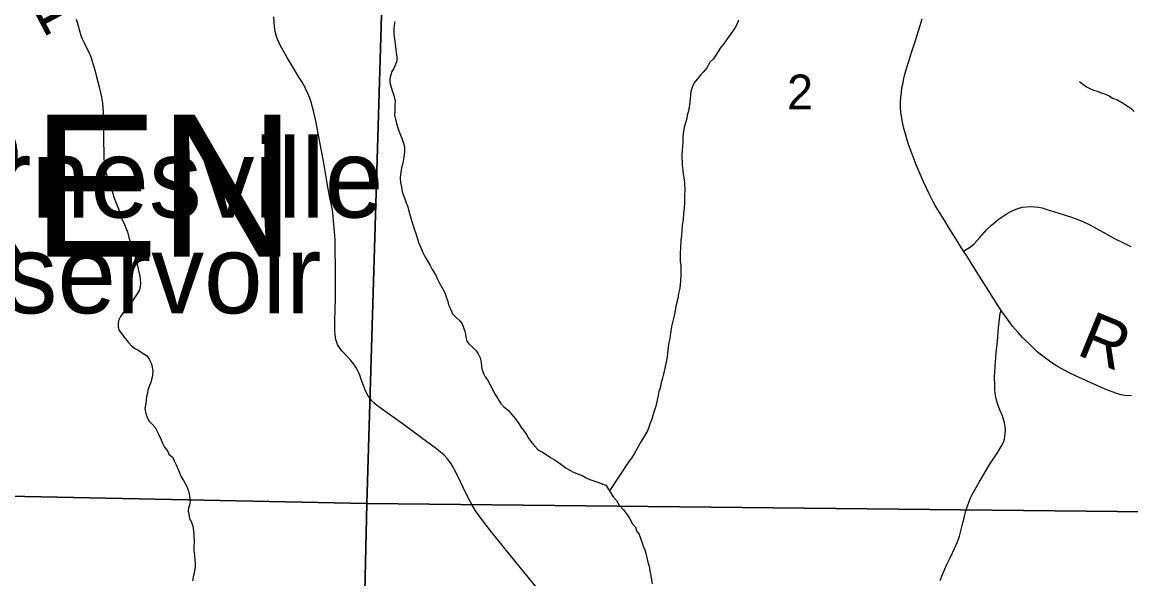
# Model space of a CAD drawing. Extents: x -7.9 to 76.1, y 0 to 22.
# Drawn here: x 4.02 to 5.35, y 19.16 to 19.828 of the extents above; entities that cross this region are included whole.
import ezdxf

# ---------------------------------------------------------------- set-up
doc = ezdxf.new("R2010")
doc.units = 0
for name, color, linetype in [('GM_X_County_Road', 7, 'Continuous'), ('GM_X_County_Road_Text', 7, 'Continuous'), ('GM_X_Minor_Lake_Text', 7, 'Continuous'), ('GM_X_Minor_River', 7, 'Continuous'), ('GM_X_Section', 7, 'Continuous'), ('GM_X_Section_Text', 7, 'Continuous'), ('GM_X_Township_Road', 7, 'Continuous'), ('GM_X_Township_Road_Text', 7, 'Continuous'), ('GM_X_Township_Text', 7, 'Continuous')]:
    doc.layers.add(name, color=color, linetype=linetype)

msp = doc.modelspace()

# ---------------------------------------------------------------- linework, layer by layer
at = {"layer": 'GM_X_County_Road'}
for points in [[(5.1493, 19.5533), (5.141, 19.5668), (5.1323, 19.5807), (5.127, 19.5893), (5.1186, 19.6025), (5.1154, 19.6078), (5.1126, 19.6129), (5.1088, 19.6203), (5.1013, 19.6361), (5.0972, 19.6456), (5.0926, 19.6565), (5.0877, 19.6696), (5.0835, 19.681), (5.0809, 19.6893), (5.0792, 19.6952), (5.0775, 19.7019), (5.0757, 19.7099), (5.0748, 19.715), (5.0743, 19.7195), (5.0739, 19.7255), (5.0738, 19.7324), (5.0741, 19.738), (5.0748, 19.7439), (5.0755, 19.7489), (5.0764, 19.7536), (5.0778, 19.7604), (5.0791, 19.7656), (5.0833, 19.7797), (5.0873, 19.7926), (5.0908, 19.8035), (5.0952, 19.8173), (5.0997, 19.8317)], [(5.1946, 19.4819), (5.1882, 19.4919), (5.1825, 19.5008), (5.1768, 19.5099), (5.1695, 19.5215), (5.1629, 19.5318), (5.1544, 19.5454), (5.1493, 19.5533)], [(5.3509, 19.3797), (5.3429, 19.3801), (5.3386, 19.3809), (5.3343, 19.382), (5.3288, 19.3839), (5.3221, 19.3865), (5.3013, 19.3957), (5.2779, 19.4065), (5.2711, 19.4099), (5.2628, 19.4144), (5.2576, 19.4176), (5.2525, 19.4212), (5.2465, 19.4257), (5.2379, 19.4325), (5.2282, 19.4418), (5.2203, 19.4496), (5.2148, 19.4557), (5.2082, 19.4633), (5.202, 19.4714), (5.1946, 19.4819)]]:
    msp.add_lwpolyline(points, dxfattribs=at)
at = {"layer": 'GM_X_Minor_River'}
for points in [[(4.0849, 19.8316), (4.0865, 19.8267), (4.0885, 19.8192), (4.0905, 19.812), (4.0921, 19.8079), (4.0949, 19.8022), (4.0972, 19.797), (4.1004, 19.7909), (4.1023, 19.7861), (4.1039, 19.7812), (4.1063, 19.7729), (4.1079, 19.7676), (4.1092, 19.7623), (4.1124, 19.7502), (4.1153, 19.7378), (4.1162, 19.7306), (4.1166, 19.7253), (4.1171, 19.7204), (4.1181, 19.6639), (4.1186, 19.6575), (4.1194, 19.6514), (4.1206, 19.6461), (4.1222, 19.6416), (4.1242, 19.6356), (4.1262, 19.6299), (4.1278, 19.625), (4.1298, 19.6178), (4.1326, 19.6107), (4.1354, 19.6039), (4.137, 19.599), (4.1401, 19.5907), (4.1425, 19.5862), (4.1441, 19.5817), (4.1464, 19.5764), (4.1481, 19.5696), (4.1501, 19.5636), (4.1521, 19.5572), (4.154, 19.5523), (4.1553, 19.5474), (4.1569, 19.5429), (4.1581, 19.5384), (4.1589, 19.5334), (4.1601, 19.5282), (4.161, 19.5232), (4.1614, 19.5195), (4.1619, 19.5145), (4.1616, 19.5107), (4.1609, 19.5069), (4.1572, 19.5008), (4.1532, 19.4947), (4.1491, 19.4893)], [(4.4671, 19.8288), (4.4661, 19.8239), (4.4658, 19.8197), (4.4659, 19.8144), (4.4663, 19.8103), (4.4672, 19.805), (4.4676, 19.8012), (4.4681, 19.7955), (4.4685, 19.7906), (4.4694, 19.7861), (4.4695, 19.7815), (4.468, 19.7769), (4.4658, 19.7723), (4.4636, 19.7685), (4.4622, 19.7647), (4.4611, 19.7601), (4.4612, 19.7556), (4.464, 19.7458), (4.4656, 19.7416), (4.4668, 19.7371), (4.4673, 19.7333), (4.467, 19.728), (4.4671, 19.7216), (4.4668, 19.7163), (4.468, 19.7114), (4.4689, 19.7064), (4.4712, 19.7)], [(4.8795, 19.8304), (4.8777, 19.8258), (4.8752, 19.8216), (4.8722, 19.8166), (4.867, 19.8093), (4.8615, 19.8013), (4.8574, 19.7966), (4.8552, 19.7928), (4.8493, 19.784), (4.8449, 19.7797), (4.8419, 19.7736), (4.8371, 19.7679), (4.8334, 19.764), (4.8297, 19.7594), (4.8264, 19.7552), (4.8242, 19.7506), (4.8224, 19.7445), (4.8214, 19.7357), (4.8208, 19.7285), (4.8194, 19.7209), (4.8179, 19.7164), (4.8173, 19.7122), (4.8144, 19.7019), (4.8134, 19.6966), (4.8127, 19.6905), (4.8125, 19.6833), (4.8119, 19.6738), (4.8116, 19.6681), (4.8118, 19.6567), (4.8127, 19.6503), (4.8131, 19.6458), (4.8139, 19.6416), (4.8148, 19.6348), (4.815, 19.6257), (4.8147, 19.6204), (4.8147, 19.6166), (4.8145, 19.6113), (4.8142, 19.6048), (4.8136, 19.5984), (4.8129, 19.5908), (4.8119, 19.5843), (4.8116, 19.5786), (4.811, 19.5718), (4.8103, 19.5665), (4.8097, 19.5562), (4.8094, 19.5517), (4.8096, 19.5403), (4.8101, 19.5362), (4.8103, 19.5248), (4.81, 19.5172), (4.809, 19.5088), (4.8076, 19.5024), (4.8066, 19.4963), (4.8041, 19.4871), (4.8035, 19.4822), (4.8021, 19.4757), (4.8003, 19.4674), (4.7992, 19.4628), (4.7979, 19.4548), (4.7969, 19.4484), (4.7958, 19.4434), (4.7951, 19.4381), (4.7941, 19.4309), (4.7938, 19.4263), (4.7928, 19.4202), (4.791, 19.4126), (4.7893, 19.4054), (4.7882, 19.4008)], [(5.2886, 19.7567), (5.2924, 19.7534), (5.297, 19.7504), (5.3016, 19.7478), (5.3054, 19.7464), (5.31, 19.7449), (5.3146, 19.7431), (5.3184, 19.742), (5.3241, 19.7394), (5.3283, 19.7368), (5.3333, 19.735), (5.3409, 19.7305), (5.3451, 19.7279), (5.3501, 19.7246), (5.3543, 19.7205)], [(4.4712, 19.7), (4.4732, 19.6944), (4.4756, 19.6887), (4.4776, 19.6827), (4.4788, 19.6782), (4.4785, 19.6725), (4.4779, 19.6657), (4.4765, 19.6588), (4.4751, 19.6531), (4.4737, 19.6455), (4.4734, 19.6402), (4.4739, 19.6353), (4.4751, 19.63), (4.4759, 19.6247), (4.4771, 19.6209), (4.4791, 19.616), (4.4807, 19.6111), (4.4827, 19.6062), (4.4839, 19.6009), (4.4855, 19.5953), (4.4871, 19.59), (4.4887, 19.5851), (4.4903, 19.5798), (4.4923, 19.5742), (4.4943, 19.5681), (4.4955, 19.5636), (4.4979, 19.5584), (4.5007, 19.5516), (4.5034, 19.5459), (4.5065, 19.5407), (4.5096, 19.5358), (4.512, 19.5313), (4.5163, 19.5242), (4.5179, 19.5204), (4.5206, 19.5148), (4.5241, 19.5084), (4.5269, 19.5031), (4.5288, 19.4982), (4.5305, 19.4926), (4.5313, 19.4888), (4.5344, 19.4832), (4.5364, 19.4779), (4.5402, 19.4738), (4.5441, 19.4705), (4.5479, 19.466), (4.5495, 19.4615), (4.5511, 19.4573), (4.5519, 19.4535), (4.5524, 19.4498), (4.5536, 19.4452), (4.5563, 19.4415), (4.5602, 19.4378), (4.5648, 19.4337), (4.5671, 19.4299), (4.5695, 19.425), (4.5707, 19.4197), (4.5712, 19.4144), (4.572, 19.4107), (4.5736, 19.4065), (4.5755, 19.4024), (4.5782, 19.3986), (4.5814, 19.3926), (4.5837, 19.3885), (4.5868, 19.3825), (4.5892, 19.3787), (4.5915, 19.3746), (4.5939, 19.3709), (4.5973, 19.3668), (4.6035, 19.3619), (4.6073, 19.3571), (4.6112, 19.3526), (4.6151, 19.3474), (4.6186, 19.3417), (4.6221, 19.3372), (4.6252, 19.3331), (4.6275, 19.3286), (4.6302, 19.3249), (4.6341, 19.32), (4.6395, 19.3144), (4.6441, 19.3119), (4.6498, 19.3085), (4.654, 19.3056), (4.6582, 19.303), (4.662, 19.3008), (4.6678, 19.2964), (4.6728, 19.2926), (4.677, 19.2904), (4.6816, 19.2879), (4.6861, 19.2861), (4.6919, 19.2839), (4.6968, 19.2813), (4.701, 19.2791), (4.7071, 19.2773), (4.7117, 19.2755), (4.7166, 19.2737), (4.7204, 19.2723), (4.7232, 19.2681), (4.7259, 19.2636), (4.729, 19.2584), (4.7329, 19.2539), (4.7364, 19.2483)], [(4.1491, 19.4893), (4.1454, 19.4847), (4.1417, 19.4801), (4.138, 19.4747), (4.1354, 19.4701), (4.1351, 19.4663), (4.1352, 19.4618), (4.1364, 19.458), (4.1395, 19.4539), (4.1434, 19.4483), (4.1476, 19.4434), (4.1515, 19.4393), (4.1553, 19.4363), (4.1599, 19.4338), (4.1652, 19.4304), (4.1691, 19.4279), (4.1725, 19.4237), (4.1753, 19.4181), (4.1761, 19.414), (4.1766, 19.4094), (4.1763, 19.4045), (4.1756, 19.4007), (4.1742, 19.3957), (4.1727, 19.3919), (4.1709, 19.3869), (4.1702, 19.3828), (4.1692, 19.3786), (4.1688, 19.3748), (4.1682, 19.3702), (4.1671, 19.3645), (4.1684, 19.3585), (4.1696, 19.3547), (4.1719, 19.3494), (4.1758, 19.3457), (4.1796, 19.3416), (4.184, 19.3326), (4.1867, 19.3266), (4.1883, 19.3228), (4.1906, 19.3179), (4.1945, 19.3134), (4.1961, 19.3097), (4.2007, 19.3056), (4.2023, 19.3014), (4.2046, 19.2966), (4.2074, 19.2902), (4.2106, 19.2823), (4.2137, 19.2778), (4.2172, 19.2714), (4.2192, 19.2665), (4.2204, 19.2623), (4.2208, 19.2582), (4.2216, 19.254), (4.221, 19.2498), (4.2195, 19.2449), (4.2192, 19.2411), (4.2209, 19.2328), (4.2236, 19.2268), (4.2248, 19.223), (4.2257, 19.2173), (4.2261, 19.2131), (4.2263, 19.2037), (4.226, 19.1991), (4.2261, 19.1942), (4.2266, 19.1878), (4.227, 19.1825), (4.2275, 19.1787), (4.2276, 19.1745), (4.2262, 19.1669), (4.2251, 19.1623), (4.2245, 19.1574)], [(4.7882, 19.4008), (4.7868, 19.3955), (4.7854, 19.3886), (4.7839, 19.3848), (4.7829, 19.3799), (4.7819, 19.3745), (4.7801, 19.3673), (4.7783, 19.3612), (4.7761, 19.3547), (4.7751, 19.3505), (4.7733, 19.3467), (4.7718, 19.3421), (4.7707, 19.3383), (4.7663, 19.3307), (4.7623, 19.3242), (4.7579, 19.3165), (4.7542, 19.31), (4.7509, 19.3046), (4.7479, 19.3008), (4.7246, 19.2657)], [(4.7364, 19.2483), (4.7414, 19.2427), (4.7452, 19.2378), (4.7487, 19.2326), (4.7523, 19.2258), (4.7557, 19.2221), (4.7569, 19.2175), (4.7601, 19.2131), (4.764, 19.2033), (4.7652, 19.1991), (4.7672, 19.1946), (4.7684, 19.1905), (4.7696, 19.1855), (4.7708, 19.1799), (4.7721, 19.175), (4.7729, 19.1697), (4.7737, 19.1659), (4.7746, 19.1606), (4.7758, 19.1538)]]:
    msp.add_lwpolyline(points, dxfattribs=at)
at = {"layer": 'GM_X_Section'}
for points in [[(4.4641, 20.2762), (4.4336, 19.2503), (3.4168, 19.2711), (3.4482, 20.2963)], [(4.4641, 20.2762), (5.4689, 20.2672), (5.4474, 19.2561), (5.4466, 19.2394), (4.4336, 19.2503)], [(3.4168, 19.2711), (4.4336, 19.2503), (4.4107, 18.2442), (3.389, 18.2623)], [(4.4336, 19.2503), (5.4466, 19.2394), (5.4216, 18.2363), (5.4207, 18.223), (4.4107, 18.2442)]]:
    msp.add_lwpolyline(points, close=True, dxfattribs=at)
at = {"layer": 'GM_X_Township_Road'}
for points in [[(4.3593, 19.7493), (4.3557, 19.7558), (4.352, 19.762), (4.3451, 19.7735), (4.3384, 19.7848), (4.3314, 19.7968), (4.329, 19.8012), (4.3278, 19.8037), (4.3262, 19.8074), (4.3251, 19.8108), (4.3239, 19.8152), (4.323, 19.8192), (4.3226, 19.8227), (4.3223, 19.8275), (4.3221, 19.8341)], [(4.6363, 19.1506), (4.6272, 19.1618), (4.6161, 19.1753), (4.6058, 19.188), (4.5973, 19.1984), (4.584, 19.215), (4.574, 19.2279), (4.5682, 19.2356), (4.5639, 19.2417), (4.5594, 19.249), (4.5552, 19.257), (4.549, 19.2697), (4.5429, 19.2823), (4.5388, 19.2907), (4.537, 19.294), (4.5348, 19.2978), (4.5328, 19.3007), (4.5301, 19.304), (4.5257, 19.3086), (4.5218, 19.3121), (4.5172, 19.3158), (4.5111, 19.3202), (4.499, 19.3291), (4.4867, 19.3382), (4.4731, 19.3482), (4.4549, 19.3613), (4.4452, 19.3683), (4.4418, 19.371), (4.4395, 19.3735), (4.4375, 19.3762), (4.4349, 19.3796), (4.433, 19.383), (4.4311, 19.3874), (4.4267, 19.399), (4.425, 19.4043), (4.4236, 19.408), (4.4223, 19.4104), (4.4203, 19.4138), (4.4177, 19.4174), (4.4141, 19.4219), (4.4103, 19.4262), (4.4053, 19.4316), (4.4034, 19.4337), (4.4014, 19.4362), (4.3997, 19.4387), (4.3983, 19.4412), (4.3974, 19.4435), (4.3964, 19.447), (4.3958, 19.4496), (4.3954, 19.4531), (4.3952, 19.4578), (4.395, 19.471), (4.3954, 19.4815), (4.3959, 19.4974), (4.396, 19.5107), (4.3959, 19.5211), (4.3958, 19.5378), (4.3956, 19.5517), (4.3953, 19.5664), (4.3947, 19.5768), (4.3936, 19.5896), (4.3931, 19.5951), (4.3921, 19.6022), (4.3896, 19.6154), (4.3872, 19.6278), (4.3843, 19.6444), (4.3814, 19.6612), (4.3791, 19.6733), (4.3755, 19.6922), (4.3725, 19.7073), (4.3697, 19.7197), (4.3683, 19.7258), (4.3667, 19.732), (4.365, 19.7367), (4.3623, 19.743), (4.3598, 19.7484), (4.3593, 19.7493)], [(5.1493, 19.5533), (5.1577, 19.5583), (5.1621, 19.5621), (5.1688, 19.5694), (5.1775, 19.5791), (5.1831, 19.5843), (5.1879, 19.5884), (5.1907, 19.5906), (5.1945, 19.5934), (5.2019, 19.5983), (5.2061, 19.6007), (5.2107, 19.6028), (5.2157, 19.6046), (5.2201, 19.6058), (5.2245, 19.6064), (5.2289, 19.6067), (5.2347, 19.6064), (5.2392, 19.6059), (5.2438, 19.6049), (5.2483, 19.6036), (5.2638, 19.5987), (5.2791, 19.5938), (5.2917, 19.589), (5.3008, 19.5848), (5.317, 19.576), (5.3298, 19.5689), (5.3436, 19.5618), (5.3501, 19.5589)], [(5.1946, 19.4819), (5.1882, 19.4919), (5.1825, 19.5008), (5.1768, 19.5099), (5.1695, 19.5215), (5.1629, 19.5318), (5.1544, 19.5454), (5.1493, 19.5533)], [(5.1214, 19.1581), (5.1241, 19.165), (5.1291, 19.1763), (5.1341, 19.1869), (5.1384, 19.1962), (5.1421, 19.2045), (5.1445, 19.2113), (5.1462, 19.2176), (5.1485, 19.227), (5.15, 19.2333), (5.1523, 19.2419), (5.1556, 19.2517), (5.1574, 19.2563), (5.1594, 19.2603), (5.1681, 19.2761), (5.181, 19.2974), (5.1905, 19.3119), (5.1945, 19.3187), (5.1972, 19.3239), (5.1984, 19.3274), (5.1989, 19.3306), (5.1994, 19.3344), (5.1996, 19.3387), (5.1993, 19.3425), (5.1986, 19.347), (5.1971, 19.3526), (5.1958, 19.3562), (5.1931, 19.3626), (5.1914, 19.3668), (5.1901, 19.3702), (5.1889, 19.3743), (5.188, 19.3781), (5.1874, 19.3829), (5.1871, 19.3867), (5.1868, 19.3942), (5.1867, 19.4003), (5.1871, 19.4091), (5.1879, 19.4205), (5.1886, 19.431), (5.19, 19.4453), (5.1915, 19.4613), (5.193, 19.4757), (5.1934, 19.4783), (5.1946, 19.4819)]]:
    msp.add_lwpolyline(points, dxfattribs=at)

# ---------------------------------------------------------------- texts
at = {"layer": 'GM_X_County_Road_Text'}
msp.add_text('R', height=0.0568, rotation=337.7137, dxfattribs=at).set_placement((5.2835, 19.4296))
at = {"layer": 'GM_X_Minor_Lake_Text'}
for s, height, rotation, p in [('Barnesville', 0.094694, 359.9945, (3.8341, 19.5935)), ('Reservoir', 0.09469, 359.9951, (3.837, 19.4786))]:
    msp.add_text(s, height=height, rotation=rotation, dxfattribs=at).set_placement(p)
at = {"layer": 'GM_X_Section_Text'}
msp.add_text('2', height=0.0419, rotation=0, dxfattribs=at).set_placement((4.9377, 19.7231))
at = {"layer": 'GM_X_Township_Road_Text'}
msp.add_text('1', height=0.0568, rotation=297.8754, dxfattribs=at).set_placement((4.0312, 19.846))
at = {"layer": 'GM_X_Township_Text'}
msp.add_text('WARREN', height=0.17045, rotation=0, dxfattribs=at).set_placement((3.3351, 19.5465))

doc.saveas('drawing.dxf')
